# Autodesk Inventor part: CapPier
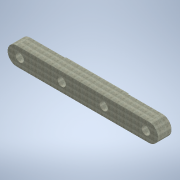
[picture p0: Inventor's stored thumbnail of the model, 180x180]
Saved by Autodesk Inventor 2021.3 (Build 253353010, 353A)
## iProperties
Created: 2021-11
Part Number: CapPier
Material: Concrete, Cast-in-Place, Gray
Document SubType Name: Modeling
Designer: u1426
Density: 2.40731 g/cm^3
Appearance: Flat - Gray 1
Author: u1426
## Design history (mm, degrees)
sketch "Sketch1"
  geometry: L1 (-4953, 685.8)-(4953, 685.8); L2 (5638.8, 0)-(5638.8, 0); L3 (4953, -685.8)-(-4953, -685.8); L4 (-5638.8, 0)-(-5638.8, 0); A1 r 685.8 centre (-4953, 0) between (-4953, 685.8) and (-5638.8, 0); A2 r 685.8 centre (-4953, 0) between (-5638.8, 0) and (-4953, -685.8); A3 r 685.8 centre (4953, 0) between (4953, -685.8) and (5638.8, 0); A4 r 685.8 centre (4953, 0) between (5638.8, 0) and (4953, 685.8); 3 further points
  constraints: 8 end point, 8 point on circle, 8 tangent, 4 centre point, 3 equal radius, 2 parallel, 1 horizontal, 1 perpendicular
  dimensions: "d0" = 5638.8 distance from line of point (0, 0) L4; "d1" = 5638.8 distance from line of point (0, 0) L2; "d2" = 685.8 distance from line of L3 point (0, 0); "d3" = 685.8 distance from line of point (0, 0) L1; "d4" = 685.8 radius of A1
extrude "Extrusion1" new body sketch "Sketch1" distance "d5" = 1016; taper "d6" = 0 deg
sketch "Sketch2"
  geometry: 5 further points
  dimensions: "d14" = 0 vertical distance of point (-4724.4, 0) point (0, 0); "d15" = 1574.8 distance of point (-1574.8, 0) point (0, 0); "d16" = 3149.6 distance of point (-4724.4, 0) point (-1574.8, 0); "d17" = 1574.8 distance of point (1574.8, 0) point (0, 0); "d18" = 3149.6 distance of point (4724.4, 0) point (1574.8, 0); "d19" = 0 vertical distance of point (1574.8, 0) point (0, 0); "d20" = 0 vertical distance of point (4724.4, 0) point (0, 0); "d21" = 0 vertical distance of point (-1574.8, 0) point (0, 0)
hole "Hole1" sketch "Sketch2" at (-4724.4, 0), (-1574.8, 0), (1574.8, 0), (4724.4, 0) diameter "d7" = 609.6; stored, may be unused: countersink angle "d11" = 82 deg, drill point angle "d13" = 0 deg; dims "d8" = 19.05, "d9" = 9.525, "d10" = 6.35, "d12" = 508
sketch "Sketch3"
  geometry: L1 (0, 1016)-(9906, 1016) reference; L2 (2616.2, 1016)-(7289.8, 1016); L3 (7289.8, 1016)-(7289.8, 1080.008); L4 (7289.8, 1080.008)-(2616.2, 1080.008); L5 (2616.2, 1080.008)-(2616.2, 1016); 2 further points
  constraints: 8 end point, 2 parallel, 1 horizontal, 1 perpendicular, 1 point on line
  dimensions: "d22" = 2336.8 distance from line of point (4953, 0) L5; "d23" = 2336.8 distance from line of point (4953, 0) L3; "d24" = 64.008 distance of L2.end L3.end
extrude "Extrusion2" join sketch "Sketch3" stored distance "d25" = 1016; taper "d26" = 0 deg
body "Solid1"
